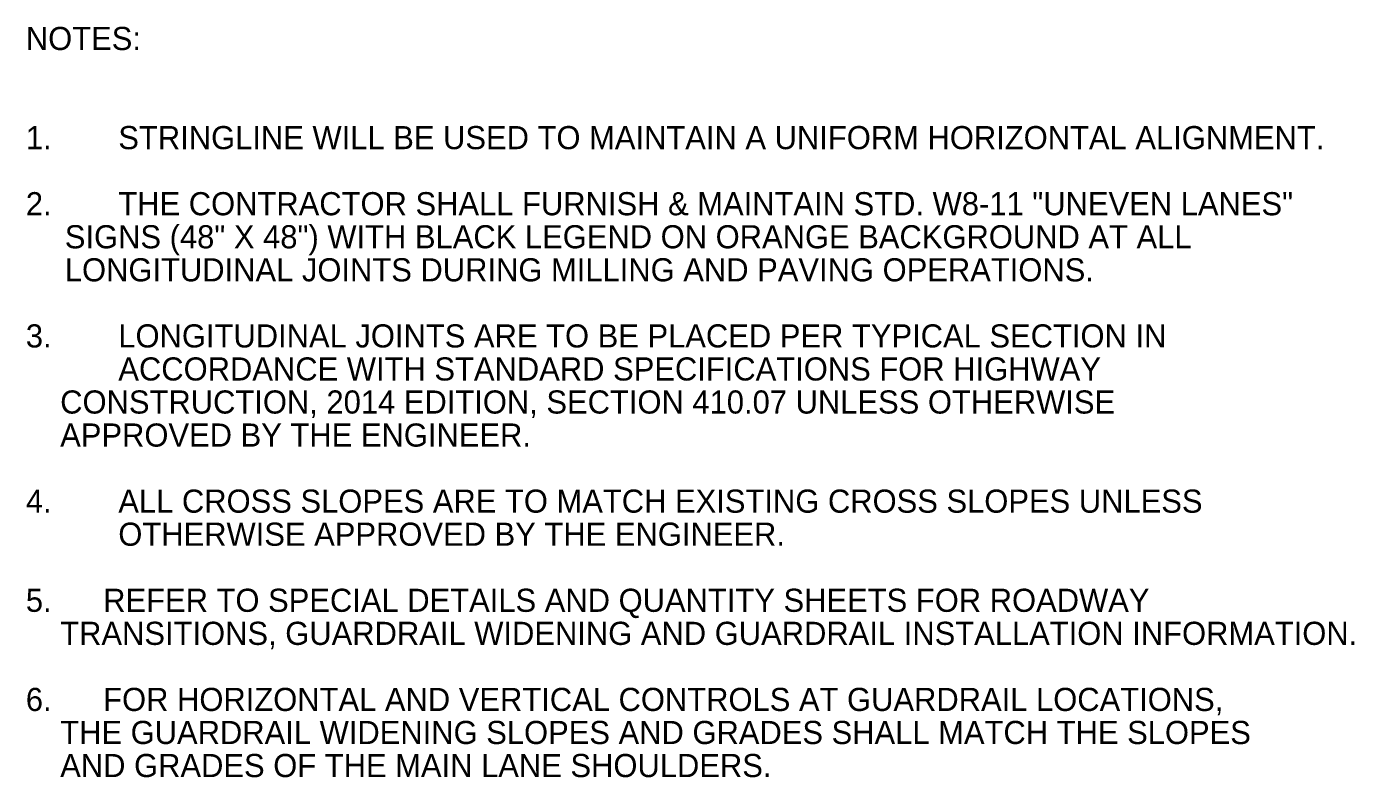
# Model space of a CAD drawing. Extents: x 544199 to 1930787, y -1968972 to 596640.
# Drawn here: x 550995.7 to 551397.7, y -1953478.6 to -1953251.4 of the extents above; entities that cross this region are included whole.
import ezdxf

# ---------------------------------------------------------------- set-up
doc = ezdxf.new("R2010")
doc.units = 0
doc.layers.add('R_Border Notes', color=7, linetype='Continuous')

msp = doc.modelspace()

# ---------------------------------------------------------------- texts
at = {"layer": 'R_Border Notes'}
for s, p in [('NOTES: ', (550995.45, -1953258.51)), ('1.', (550995.45, -1953288.51)), ('STRINGLINE WILL BE USED TO MAINTAIN A UNIFORM HORIZONTAL ALIGNMENT.', (551023.45, -1953288.51)), ('2.', (550995.45, -1953308.51)), ('THE CONTRACTOR SHALL FURNISH & MAINTAIN STD. W8-11 "UNEVEN LANES" ', (551023.45, -1953308.51)), ('    SIGNS (48" X 48") WITH BLACK LEGEND ON ORANGE BACKGROUND AT ALL ', (550996.85, -1953318.51)), ('    LONGITUDINAL JOINTS DURING MILLING AND PAVING OPERATIONS.', (550996.85, -1953328.51)), ('3.', (550995.45, -1953348.51)), ('LONGITUDINAL JOINTS ARE TO BE PLACED PER TYPICAL SECTION IN ', (551023.45, -1953348.51)), ('ACCORDANCE WITH STANDARD SPECIFICATIONS FOR HIGHWAY', (551023.45, -1953358.51)), ('    CONSTRUCTION, 2014 EDITION, SECTION 410.07 UNLESS OTHERWISE', (550995.45, -1953368.51)), ('    APPROVED BY THE ENGINEER.', (550995.45, -1953378.51)), ('4.', (550995.45, -1953398.51)), ('ALL CROSS SLOPES ARE TO MATCH EXISTING CROSS SLOPES UNLESS ', (551023.45, -1953398.51)), ('OTHERWISE APPROVED BY THE ENGINEER.', (551023.45, -1953408.51)), ('5.      REFER TO SPECIAL DETAILS AND QUANTITY SHEETS FOR ROADWAY', (550995.45, -1953428.51)), ('    TRANSITIONS, GUARDRAIL WIDENING AND GUARDRAIL INSTALLATION INFORMATION.', (550995.45, -1953438.51)), ('6.      FOR HORIZONTAL AND VERTICAL CONTROLS AT GUARDRAIL LOCATIONS,', (550995.45, -1953458.51)), ('    THE GUARDRAIL WIDENING SLOPES AND GRADES SHALL MATCH THE SLOPES', (550995.45, -1953468.51)), ('    AND GRADES OF THE MAIN LANE SHOULDERS.  ', (550995.45, -1953478.51))]:
    msp.add_text(s, height=7, dxfattribs=at).set_placement(p)

doc.saveas('drawing.dxf')
